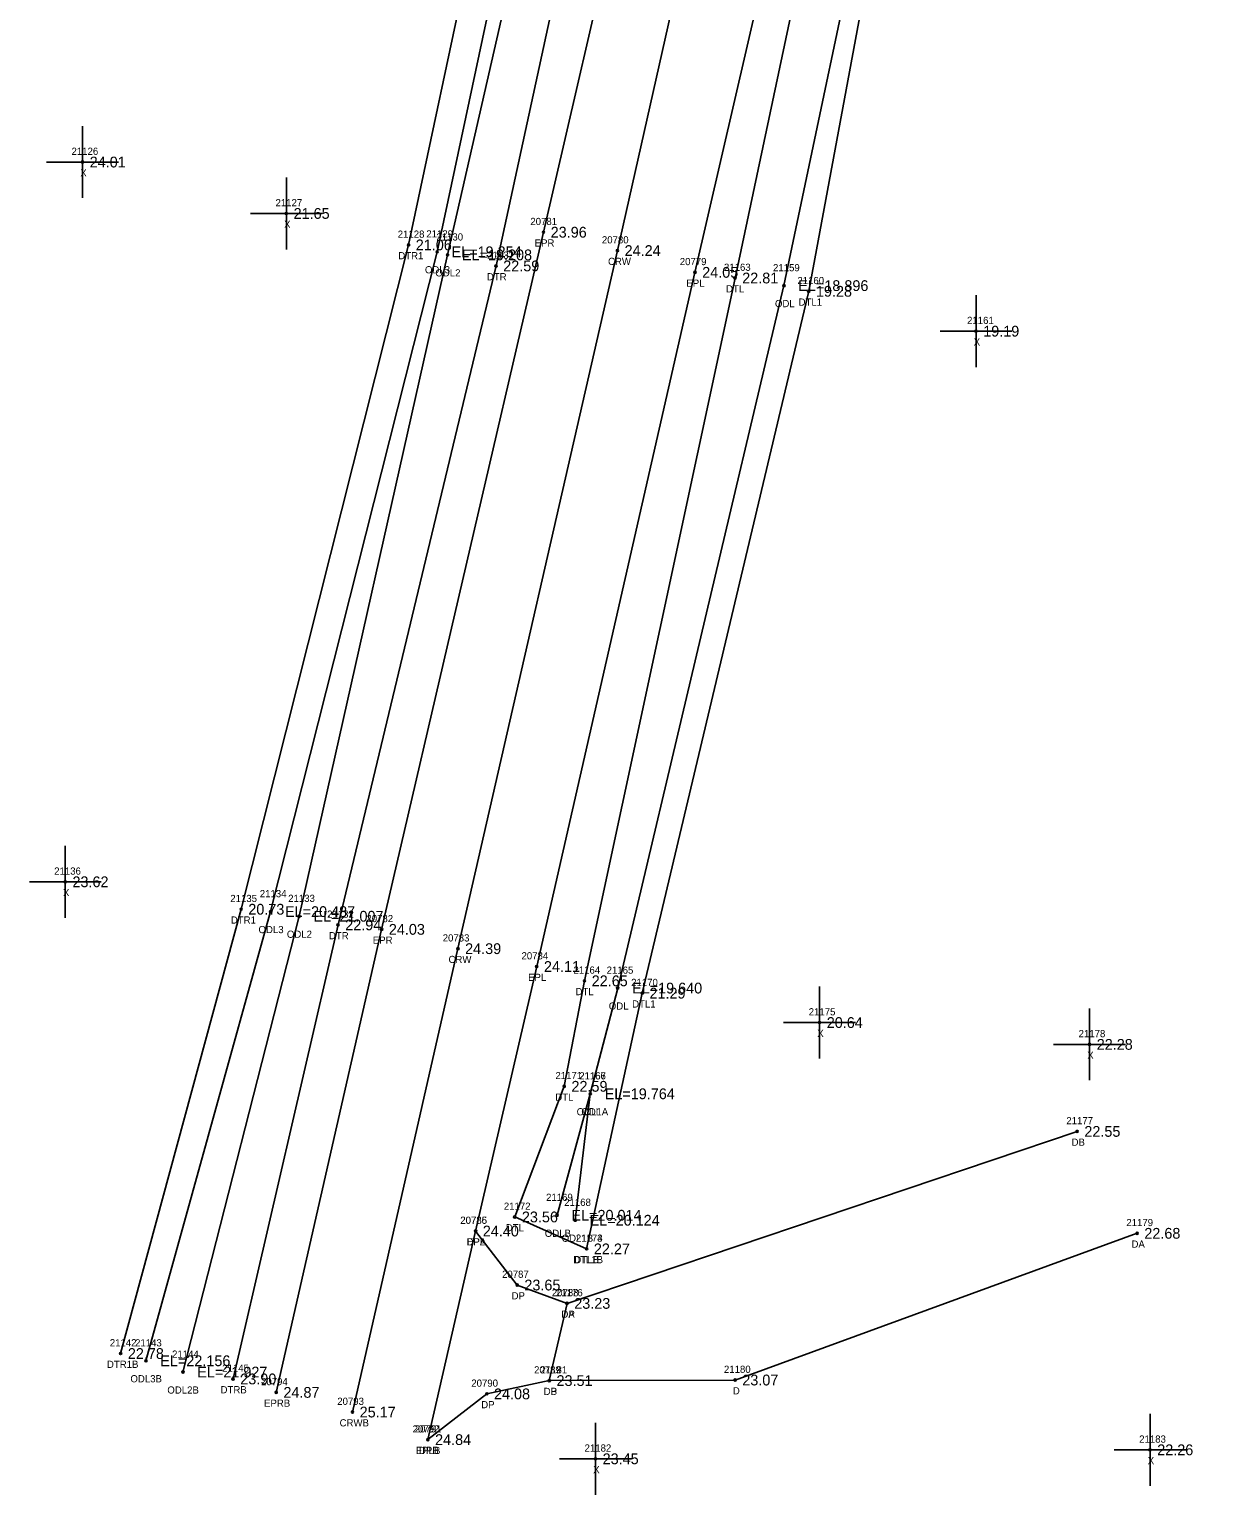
# Model space of a CAD drawing. Extents: x 2655177 to 2656219, y 761780 to 764748.
# Drawn here: x 2655339.1 to 2655506.1, y 761779.7 to 761983.8 of the extents above; entities that cross this region are included whole.
import ezdxf

# ---------------------------------------------------------------- set-up
doc = ezdxf.new("R2010")
doc.units = 0
for name, color, linetype in [('RD_DTM_BkLn1', 7, 'Continuous'), ('RD_EX_Driveway', 7, 'Continuous'), ('RD_EX_Driveway_txCode', 7, 'Continuous'), ('RD_EX_H2O', 7, 'Continuous'), ('RD_EX_H2O_txCode', 7, 'Continuous'), ('RD_EX_Misc', 7, 'Continuous'), ('RD_EX_Misc_txCode', 7, 'Continuous'), ('RD_EX_Road', 7, 'Continuous'), ('RD_EX_Road_txCode', 7, 'Continuous'), ('RD_EX_TX_Driveway_ELEV', 7, 'Continuous'), ('RD_EX_TX_H2O_ELEV', 7, 'Continuous'), ('RD_EX_TX_Misc_ELEV', 7, 'Continuous'), ('RD_EX_TX_Road_ELEV', 7, 'Continuous'), ('RD_HC_Survey_ELEV', 7, 'Continuous'), ('RD_HC_Survey_txCode', 7, 'Continuous'), ('RD_SMD_Locator', 7, 'Continuous')]:
    doc.layers.add(name, color=color, linetype=linetype)

msp = doc.modelspace()

# ---------------------------------------------------------------- linework, layer by layer
at = {"layer": 'RD_DTM_BkLn1'}
msp.add_lwpolyline([(2655711.06, 763230.3), (2655703.38, 763195.9), (2655681.97, 763099.65), (2655659.44, 762998.39), (2655637.72, 762903.26), (2655615.94, 762806.28), (2655593.94, 762710.45), (2655572.67, 762616.37), (2655551.12, 762519.58), (2655528.83, 762422.13), (2655507.58, 762326.81), (2655486.01, 762234.2), (2655464.77, 762141.12), (2655442.2, 762047.28), (2655420.99, 761952.95), (2655398.79, 761855.74), (2655384.11, 761791.21)], dxfattribs=at)
at = {"layer": 'RD_EX_Driveway'}
msp.add_line((2655413.98, 761806.34), (2655484.99, 761830.29), dxfattribs=at)
for points in [[(2655401.25, 761816.42), (2655407.04, 761808.9), (2655413.98, 761806.34), (2655411.51, 761795.59), (2655402.81, 761793.74), (2655394.61, 761787.37)], [(2655493.34, 761816.1), (2655437.37, 761795.67), (2655411.51, 761795.59)]]:
    msp.add_lwpolyline(points, dxfattribs=at)
at = {"layer": 'RD_EX_H2O'}
msp.add_line((2655417.22, 761835.53), (2655415.12, 761817.92), dxfattribs=at)
for points in [[(2655442.27, 762168.74), (2655436.99, 762148.08), (2655416.08, 762052.07), (2655414.04, 762038.09), (2655395.9, 761952.78), (2655372.72, 761860.9), (2655355.36, 761798.35)], [(2655444.57, 762168.7), (2655440.7, 762146.82), (2655420.83, 762052.86), (2655421.66, 762047.52), (2655418.56, 762045.31), (2655397.35, 761952.35), (2655376.67, 761860.25), (2655360.51, 761796.78)], [(2655450.32, 762170.31), (2655447.51, 762145.05), (2655428.44, 762061.32), (2655427.05, 762050.54), (2655425.43, 762042.76), (2655423.63, 762041.01), (2655404.09, 761950.81), (2655382.1, 761859.05), (2655367.49, 761795.82)], [(2655476.07, 762118.66), (2655457.95, 762043.6), (2655455.32, 762034.02), (2655437.36, 761949.13), (2655416.41, 761851.26), (2655413.59, 761836.57), (2655406.69, 761818.38), (2655416.71, 761813.93)], [(2655480.29, 762116.19), (2655463.79, 762041.53), (2655456.91, 762008.75), (2655444.17, 761948.07), (2655421.03, 761850.25), (2655417.22, 761835.53), (2655412.59, 761818.61)], [(2655386.96, 762044.53), (2655409.62, 762037.18), (2655391.92, 761953.74), (2655368.61, 761861.23), (2655351.84, 761799.36)], [(2655458.25, 762004.65), (2655447.62, 761947.28), (2655424.45, 761849.54), (2655416.71, 761813.93)]]:
    msp.add_lwpolyline(points, dxfattribs=at)
at = {"layer": 'RD_EX_Misc'}
for p, q in [((2655346.53, 761960.28), (2655346.53, 761970.28)), ((2655341.53, 761965.28), (2655351.53, 761965.28)), ((2655374.91, 761953.12), (2655374.91, 761963.12)), ((2655369.91, 761958.12), (2655379.91, 761958.12)), ((2655470.91, 761936.73), (2655470.91, 761946.73)), ((2655465.91, 761941.73), (2655475.91, 761941.73)), ((2655344.13, 761860.05), (2655344.13, 761870.05)), ((2655339.13, 761865.05), (2655349.13, 761865.05)), ((2655449.13, 761840.45), (2655449.13, 761850.45)), ((2655486.71, 761837.41), (2655486.71, 761847.41)), ((2655444.13, 761845.45), (2655454.13, 761845.45)), ((2655481.71, 761842.41), (2655491.71, 761842.41)), ((2655495.13, 761780.95), (2655495.13, 761790.95)), ((2655417.93, 761779.7), (2655417.93, 761789.7)), ((2655412.93, 761784.7), (2655422.93, 761784.7)), ((2655490.13, 761785.95), (2655500.13, 761785.95))]:
    msp.add_line(p, q, dxfattribs=at)
at = {"layer": 'RD_EX_Road'}
for points in [[(2655700.99, 763232.28), (2655693.55, 763198.57), (2655671.65, 763102.04), (2655649.04, 763001.06), (2655627.27, 762906.23), (2655605, 762809.37), (2655598.99, 762783.09), (2655583.65, 762714.14), (2655561.97, 762618.32), (2655556.36, 762593.84), (2655548.11, 762557.14), (2655540.1, 762522.48), (2655518.03, 762425.04), (2655496.48, 762329.56), (2655475.55, 762236.62), (2655473.2, 762226.14), (2655466.57, 762197.5), (2655460.06, 762168.16), (2655454.26, 762143.78), (2655432.5, 762049.88), (2655410.7, 761955.51), (2655388.17, 761858.43), (2655373.5, 761793.95)], [(2655576.46, 762583.32), (2655561.41, 762517.24), (2655539.15, 762414.81), (2655531.98, 762386.15), (2655517.98, 762324.29), (2655508.17, 762280.15), (2655501.46, 762251.6), (2655496.92, 762232.09), (2655477.2, 762144.97), (2655472.14, 762122.52), (2655453.74, 762045.1), (2655431.79, 761949.92), (2655409.76, 761853.25), (2655401.25, 761816.42), (2655394.61, 761787.37)]]:
    msp.add_lwpolyline(points, dxfattribs=at)
at = {"layer": 'RD_SMD_Locator'}
for centre in [(2655346.53, 761965.28), (2655374.91, 761958.12), (2655410.7, 761955.51), (2655391.92, 761953.74), (2655395.9, 761952.78), (2655397.35, 761952.35), (2655420.99, 761952.95), (2655404.09, 761950.81), (2655431.79, 761949.92), (2655437.36, 761949.13), (2655444.17, 761948.07), (2655447.62, 761947.28), (2655470.91, 761941.73), (2655344.13, 761865.05), (2655368.61, 761861.23), (2655372.72, 761860.9), (2655376.67, 761860.25), (2655382.1, 761859.05), (2655388.17, 761858.43), (2655398.79, 761855.74), (2655409.76, 761853.25), (2655416.41, 761851.26), (2655421.03, 761850.25), (2655424.45, 761849.54), (2655449.13, 761845.45), (2655486.71, 761842.41), (2655413.59, 761836.57), (2655417.22, 761835.53), (2655417.22, 761835.53), (2655484.99, 761830.29), (2655406.69, 761818.38), (2655412.59, 761818.61), (2655415.12, 761817.92), (2655401.25, 761816.42), (2655401.25, 761816.42), (2655493.34, 761816.1), (2655416.71, 761813.93), (2655416.71, 761813.93), (2655407.04, 761808.9), (2655413.98, 761806.34), (2655413.98, 761806.34), (2655351.84, 761799.36), (2655355.36, 761798.35), (2655360.51, 761796.78), (2655367.49, 761795.82), (2655411.51, 761795.59), (2655411.51, 761795.59), (2655437.37, 761795.67), (2655373.5, 761793.95), (2655402.81, 761793.74), (2655384.11, 761791.21), (2655394.61, 761787.37), (2655394.61, 761787.37), (2655417.93, 761784.7), (2655495.13, 761785.95)]:
    msp.add_circle(centre, 0.15, dxfattribs=at)

# ---------------------------------------------------------------- texts
at = {"layer": 'RD_EX_Driveway_txCode'}
for s, p in [('21177', (2655483.48, 761831.29)), ('DB', (2655484.21, 761828.29)), ('20786', (2655399.11, 761817.42)), ('21179', (2655491.83, 761817.1)), ('DPA', (2655399.98, 761814.42)), ('DA', (2655492.55, 761814.1)), ('20787', (2655404.93, 761809.9)), ('DP', (2655406.26, 761806.9)), ('20788', (2655411.86, 761807.34)), ('21176', (2655412.44, 761807.34)), ('DA', (2655413.18, 761804.34)), ('DP', (2655413.2, 761804.34)), ('20789', (2655409.39, 761796.59)), ('21181', (2655410.28, 761796.59)), ('21180', (2655435.82, 761796.67)), ('20790', (2655400.65, 761794.74)), ('DP', (2655410.73, 761793.59)), ('DB', (2655410.73, 761793.59)), ('D', (2655437.06, 761793.67)), ('DP', (2655402.03, 761791.74)), ('20791', (2655392.78, 761788.37)), ('DPB', (2655393.36, 761785.37))]:
    msp.add_text(s, height=1, dxfattribs=at).set_placement(p)
at = {"layer": 'RD_EX_H2O_txCode'}
for s, p in [('21128', (2655390.41, 761954.74)), ('21129', (2655394.39, 761954.78)), ('21130', (2655395.79, 761954.35)), ('DTR1', (2655390.49, 761951.74)), ('21131', (2655402.86, 761951.81)), ('ODL3', (2655394.2, 761949.78)), ('ODL2', (2655395.65, 761949.35)), ('21163', (2655435.82, 761950.13)), ('21159', (2655442.65, 761950.07)), ('DTR', (2655402.82, 761948.81)), ('DTL', (2655436.11, 761947.13)), ('21160', (2655446.04, 761948.28)), ('ODL', (2655442.92, 761945.07)), ('DTL1', (2655446.21, 761945.28)), ('21135', (2655367.1, 761862.23)), ('21134', (2655371.21, 761862.9)), ('21133', (2655375.16, 761862.25)), ('DTR1', (2655367.18, 761859.23)), ('21132', (2655380.58, 761860.05)), ('ODL3', (2655371.03, 761857.9)), ('ODL2', (2655374.98, 761857.25)), ('DTR', (2655380.83, 761857.05)), ('21164', (2655414.87, 761852.26)), ('21165', (2655419.49, 761852.25)), ('DTL', (2655415.16, 761849.26)), ('21170', (2655422.9, 761850.54)), ('ODL', (2655419.79, 761847.25)), ('DTL1', (2655423.04, 761847.54)), ('21171', (2655412.36, 761837.57)), ('21166', (2655415.66, 761837.53)), ('21167', (2655415.68, 761837.53)), ('DTL', (2655412.34, 761834.57)), ('ODL1A', (2655415.32, 761832.53)), ('ODL', (2655415.97, 761832.53)), ('21169', (2655411.06, 761820.61)), ('21172', (2655405.18, 761819.38)), ('21168', (2655413.58, 761819.92)), ('DTL', (2655405.45, 761816.38)), ('ODLB', (2655410.88, 761815.61)), ('ODL1B', (2655413.23, 761814.92)), ('21173', (2655415.2, 761814.93)), ('21174', (2655415.2, 761814.93)), ('DTL1B', (2655414.83, 761811.93)), ('DTLB', (2655414.99, 761811.93)), ('21142', (2655350.33, 761800.36)), ('21143', (2655353.85, 761800.35)), ('21144', (2655359, 761798.78)), ('DTR1B', (2655349.93, 761797.36)), ('21145', (2655365.98, 761796.82)), ('ODL3B', (2655353.2, 761795.35)), ('ODL2B', (2655358.34, 761793.78)), ('DTRB', (2655365.75, 761793.82))]:
    msp.add_text(s, height=1, dxfattribs=at).set_placement(p)
at = {"layer": 'RD_EX_Misc_txCode'}
for s, p in [('21126', (2655345, 761966.28)), ('X', (2655346.22, 761963.28)), ('21127', (2655373.4, 761959.12)), ('X', (2655374.59, 761956.12)), ('21161', (2655469.66, 761942.73)), ('X', (2655470.59, 761939.73)), ('21136', (2655342.59, 761866.05)), ('X', (2655343.81, 761863.05)), ('21175', (2655447.62, 761846.45)), ('X', (2655448.81, 761843.45)), ('21178', (2655485.19, 761843.41)), ('X', (2655486.39, 761840.41)), ('21182', (2655416.42, 761785.7)), ('21183', (2655493.62, 761786.95)), ('X', (2655494.81, 761783.95)), ('X', (2655417.62, 761782.7))]:
    msp.add_text(s, height=1, dxfattribs=at).set_placement(p)
at = {"layer": 'RD_EX_Road_txCode'}
for s, p in [('20781', (2655408.87, 761956.51)), ('EPR', (2655409.47, 761953.51)), ('20779', (2655429.67, 761950.92)), ('EPL', (2655430.59, 761947.92)), ('20782', (2655386.05, 761859.43)), ('EPR', (2655386.94, 761856.43)), ('20784', (2655407.64, 761854.25)), ('EPL', (2655408.55, 761851.25)), ('20785', (2655399.13, 761817.42)), ('EPL', (2655400.04, 761814.42)), ('20794', (2655371.38, 761794.95)), ('EPRB', (2655371.8, 761791.95)), ('20792', (2655392.49, 761788.37)), ('EPLB', (2655392.93, 761785.37))]:
    msp.add_text(s, height=1, dxfattribs=at).set_placement(p)
at = {"layer": 'RD_EX_TX_Driveway_ELEV'}
for s, p in [('22.55', (2655485.99, 761829.54)), ('24.40', (2655402.25, 761815.67)), ('22.68', (2655494.34, 761815.35)), ('23.65', (2655408.04, 761808.15)), ('23.23', (2655414.98, 761805.59)), ('23.23', (2655414.98, 761805.59)), ('23.51', (2655412.51, 761794.84)), ('23.51', (2655412.51, 761794.84)), ('23.07', (2655438.37, 761794.92)), ('24.08', (2655403.81, 761792.99)), ('24.84', (2655395.61, 761786.62))]:
    msp.add_text(s, height=1.5, dxfattribs=at).set_placement(p)
at = {"layer": 'RD_EX_TX_H2O_ELEV'}
for s, p in [('21.06', (2655392.92, 761952.99)), ('EL=19.254', (2655397.9, 761952.03)), ('EL=19.208', (2655399.35, 761951.6)), ('22.59', (2655405.09, 761950.06)), ('22.81', (2655438.36, 761948.38)), ('EL=18.896', (2655446.17, 761947.32)), ('19.28', (2655448.62, 761946.53)), ('20.73', (2655369.61, 761860.48)), ('EL=20.487', (2655374.72, 761860.15)), ('EL=21.007', (2655378.67, 761859.5)), ('22.94', (2655383.1, 761858.3)), ('22.65', (2655417.41, 761850.51)), ('EL=19.640', (2655423.03, 761849.5)), ('21.29', (2655425.45, 761848.79)), ('22.59', (2655414.59, 761835.82)), ('EL=19.764', (2655419.22, 761834.78)), ('EL=19.764', (2655419.22, 761834.78)), ('EL=20.014', (2655414.59, 761817.86)), ('23.56', (2655407.69, 761817.63)), ('EL=20.124', (2655417.12, 761817.17)), ('22.27', (2655417.71, 761813.18)), ('22.27', (2655417.71, 761813.18)), ('22.78', (2655352.84, 761798.61)), ('EL=22.156', (2655357.36, 761797.6)), ('EL=21.927', (2655362.51, 761796.03)), ('23.90', (2655368.49, 761795.07))]:
    msp.add_text(s, height=1.5, dxfattribs=at).set_placement(p)
at = {"layer": 'RD_EX_TX_Misc_ELEV'}
for s, p in [('24.01', (2655347.53, 761964.53)), ('21.65', (2655375.91, 761957.37)), ('19.19', (2655471.91, 761940.98)), ('23.62', (2655345.13, 761864.3)), ('20.64', (2655450.13, 761844.7)), ('22.28', (2655487.71, 761841.66)), ('22.26', (2655496.13, 761785.2)), ('23.45', (2655418.93, 761783.95))]:
    msp.add_text(s, height=1.5, dxfattribs=at).set_placement(p)
at = {"layer": 'RD_EX_TX_Road_ELEV'}
for s, p in [('23.96', (2655411.7, 761954.76)), ('24.05', (2655432.79, 761949.17)), ('24.03', (2655389.17, 761857.68)), ('24.11', (2655410.76, 761852.5)), ('24.40', (2655402.25, 761815.67)), ('24.87', (2655374.5, 761793.2)), ('24.84', (2655395.61, 761786.62))]:
    msp.add_text(s, height=1.5, dxfattribs=at).set_placement(p)
at = {"layer": 'RD_HC_Survey_ELEV'}
for s, p in [('24.24', (2655421.99, 761952.2)), ('24.39', (2655399.79, 761854.99)), ('25.17', (2655385.11, 761790.46))]:
    msp.add_text(s, height=1.5, dxfattribs=at).set_placement(p)
at = {"layer": 'RD_HC_Survey_txCode'}
for s, p in [('20780', (2655418.83, 761953.95)), ('CRW', (2655419.68, 761950.95)), ('20783', (2655396.67, 761856.74)), ('CRW', (2655397.48, 761853.74)), ('20793', (2655381.99, 761792.21)), ('CRWB', (2655382.32, 761789.21))]:
    msp.add_text(s, height=1, dxfattribs=at).set_placement(p)

doc.saveas('drawing.dxf')
